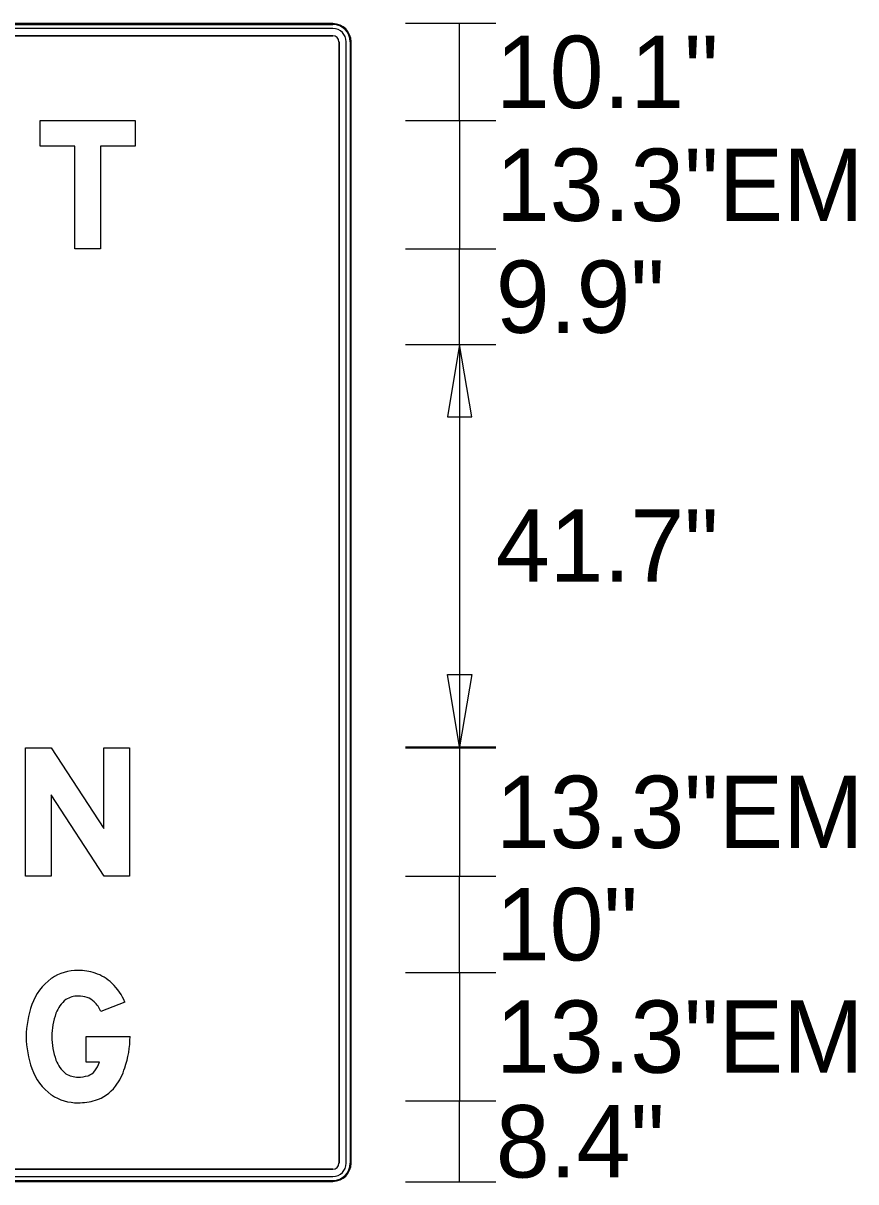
# Model space of a CAD drawing. Extents: x 1806251 to 1809821, y 414895 to 422886.
# Drawn here: x 1809677.976 to 1809678.839, y 415051.78 to 415052.981 of the extents above; entities that cross this region are included whole.
import ezdxf

# ---------------------------------------------------------------- set-up
doc = ezdxf.new("R2010")
doc.units = 0
for name, color, linetype in [('GSBWFILL', 7, 'Continuous'), ('GSCOLORFILL', 7, 'Continuous'), ('GSDIMS', 7, 'Continuous'), ('GSOUTLINE', 7, 'Continuous')]:
    doc.layers.add(name, color=color, linetype=linetype)

msp = doc.modelspace()

# ---------------------------------------------------------------- linework, layer by layer
at = {"layer": 'GSBWFILL'}
for p, q in [((1809678.2972, 415052.9805), (1809676.8938, 415052.9805)), ((1809678.2972, 415052.9755), (1809676.8938, 415052.9755)), ((1809676.8938, 415052.968), (1809678.2972, 415052.968)), ((1809678.3035, 415052.9617), (1809678.3035, 415051.7993)), ((1809678.311, 415051.7993), (1809678.311, 415052.9617)), ((1809678.316, 415051.7993), (1809678.316, 415052.9617)), ((1809678.2972, 415051.793), (1809676.8938, 415051.793)), ((1809676.8938, 415051.7855), (1809678.2972, 415051.7855)), ((1809676.8938, 415051.7805), (1809678.2972, 415051.7805))]:
    msp.add_line(p, q, dxfattribs=at)
for points in [[(1809678.0563, 415052.747), (1809678.0297, 415052.747), (1809678.0297, 415052.8534), (1809677.9938, 415052.8534), (1809677.9938, 415052.88), (1809678.0922, 415052.88), (1809678.0922, 415052.8534), (1809678.0563, 415052.8534)], [(1809677.9786, 415052.23), (1809678.0052, 415052.23), (1809678.0598, 415052.1462), (1809678.0598, 415052.23), (1809678.0864, 415052.23), (1809678.0864, 415052.097), (1809678.0601, 415052.097), (1809678.0052, 415052.1812), (1809678.0052, 415052.097), (1809677.9786, 415052.097)]]:
    msp.add_lwpolyline(points, close=True, dxfattribs=at)
for points in [[(1809678.0817, 415051.9662), (1809678.0568, 415051.9567)], [(1809678.0553, 415051.9039), (1809678.0415, 415051.9039), (1809678.0415, 415051.9305), (1809678.087, 415051.9305)]]:
    msp.add_lwpolyline(points, dxfattribs=at)
for centre, radius, start, end in [((1809678.2972, 415052.9617), 0.0188, 0, 90), ((1809678.2972, 415052.9617), 0.0138, 0, 90), ((1809678.2972, 415052.9617), 0.00625, 0, 90), ((1809678.2972, 415051.7993), 0.0138, 270, 0), ((1809678.2972, 415051.7993), 0.00625, 270, 0), ((1809678.2972, 415051.7993), 0.0188, 270, 0)]:
    msp.add_arc(centre, radius, start, end, dxfattribs=at)
for centre, major_axis, start_param, end_param in [((1809678.0331, 415051.9482), (0, 0.0509), 6.282946, 6.85835), ((1809678.0331, 415051.9419), (0, 0.0572), 5.968128, 6.283185), ((1809678.0368, 415051.9533), (0, 0.0452), 5.51497, 5.968128), ((1809678.0397, 415051.9442), (0, 0.0579), 0.634329, 1.227998), ((1809678.0269, 415051.943), (0, 0.0595), 5.112302, 5.51497), ((1809678.0397, 415051.9442), (0, 0.0313), 0.660238, 1.227998), ((1809678.0331, 415051.9481), (0, 0.0244), 6.282815, 6.826868), ((1809678.0331, 415051.9419), (0, 0.0306), 5.968128, 6.283185), ((1809678.0368, 415051.9533), (0, 0.0186), 5.51497, 5.968128), ((1809678.0844, 415051.9289), (0, 0.1051), 1.233536, 1.555728), ((1809678.0269, 415051.943), (0, 0.0329), 5.141395, 5.51497), ((1809678.0784, 415051.9305), (0, 0.0724), 1.228714, 1.570494), ((1809678.0844, 415051.9321), (0, 0.1051), 1.585865, 1.908057), ((1809678.0784, 415051.9305), (0, 0.0724), 1.571362, 1.913142), ((1809677.9897, 415051.9305), (0, 0.0973), 4.373891, 4.712389), ((1809678.0397, 415051.9168), (0, 0.0579), 1.913595, 2.507264), ((1809678.0397, 415051.9168), (0, 0.0313), 1.913852, 2.481612), ((1809678.0215, 415051.9166), (0, 0.0362), 4.071542, 4.353904), ((1809678.0215, 415051.9166), (0, 0.0628), 4.071542, 4.414751), ((1809678.0331, 415051.9128), (0, 0.0243), 2.597779, 3.141832), ((1809678.0331, 415051.924), (0, 0.0355), 3.141503, 3.435382), ((1809678.0394, 415051.9032), (0, 0.0138), 3.435472, 4.071542), ((1809678.0394, 415051.9032), (0, 0.0404), 3.435472, 4.071542), ((1809678.0331, 415051.9128), (0, 0.0509), 2.566428, 3.141832), ((1809678.0331, 415051.924), (0, 0.0621), 3.141593, 3.435472)]:
    msp.add_ellipse(centre, major_axis=major_axis, ratio=0.999994, start_param=start_param, end_param=end_param, dxfattribs=at)
at = {"layer": 'GSCOLORFILL'}
for p, q in [((1809678.2972, 415052.9805), (1809676.8938, 415052.9805)), ((1809678.2972, 415052.9805), (1809676.8938, 415052.9805)), ((1809676.8938, 415052.9797), (1809678.2972, 415052.9797)), ((1809678.2972, 415052.9755), (1809676.8938, 415052.9755)), ((1809676.8938, 415052.968), (1809678.2972, 415052.968)), ((1809678.3035, 415052.9617), (1809678.3035, 415051.7993)), ((1809678.311, 415051.7993), (1809678.311, 415052.9617)), ((1809678.3152, 415052.9617), (1809678.3152, 415051.7993)), ((1809678.316, 415051.7993), (1809678.316, 415052.9617)), ((1809678.316, 415051.7993), (1809678.316, 415052.9617)), ((1809678.2972, 415051.793), (1809676.8938, 415051.793)), ((1809676.8938, 415051.7855), (1809678.2972, 415051.7855)), ((1809678.2972, 415051.7812), (1809676.8938, 415051.7812)), ((1809676.8938, 415051.7805), (1809678.2972, 415051.7805)), ((1809676.8938, 415051.7805), (1809678.2972, 415051.7805))]:
    msp.add_line(p, q, dxfattribs=at)
for points in [[(1809678.0563, 415052.747), (1809678.0297, 415052.747), (1809678.0297, 415052.8534), (1809677.9938, 415052.8534), (1809677.9938, 415052.88), (1809678.0922, 415052.88), (1809678.0922, 415052.8534), (1809678.0563, 415052.8534)], [(1809677.9786, 415052.23), (1809678.0052, 415052.23), (1809678.0598, 415052.1462), (1809678.0598, 415052.23), (1809678.0864, 415052.23), (1809678.0864, 415052.097), (1809678.0601, 415052.097), (1809678.0052, 415052.1812), (1809678.0052, 415052.097), (1809677.9786, 415052.097)]]:
    msp.add_lwpolyline(points, close=True, dxfattribs=at)
for points in [[(1809678.0817, 415051.9662), (1809678.0568, 415051.9567)], [(1809678.0553, 415051.9039), (1809678.0415, 415051.9039), (1809678.0415, 415051.9305), (1809678.087, 415051.9305)]]:
    msp.add_lwpolyline(points, dxfattribs=at)
for centre, radius, start, end in [((1809678.2972, 415052.9617), 0.0188, 0, 90), ((1809678.2972, 415052.9617), 0.0188, 0, 90), ((1809678.2972, 415052.9617), 0.018, 0, 90), ((1809678.2972, 415052.9617), 0.0138, 0, 90), ((1809678.2972, 415052.9617), 0.00625, 0, 90), ((1809678.2972, 415051.7993), 0.0188, 270, 0), ((1809678.2972, 415051.7993), 0.0138, 270, 0), ((1809678.2972, 415051.7993), 0.00625, 270, 0), ((1809678.2972, 415051.7993), 0.0188, 270, 0), ((1809678.2972, 415051.7993), 0.018, 270, 0)]:
    msp.add_arc(centre, radius, start, end, dxfattribs=at)
for centre, major_axis, start_param, end_param in [((1809678.0331, 415051.9482), (0, 0.0509), 6.282946, 6.85835), ((1809678.0331, 415051.9419), (0, 0.0572), 5.968128, 6.283185), ((1809678.0368, 415051.9533), (0, 0.0452), 5.51497, 5.968128), ((1809678.0397, 415051.9442), (0, 0.0579), 0.634329, 1.227998), ((1809678.0269, 415051.943), (0, 0.0595), 5.112302, 5.51497), ((1809678.0397, 415051.9442), (0, 0.0313), 0.660238, 1.227998), ((1809678.0331, 415051.9481), (0, 0.0244), 6.282815, 6.826868), ((1809678.0331, 415051.9419), (0, 0.0306), 5.968128, 6.283185), ((1809678.0368, 415051.9533), (0, 0.0186), 5.51497, 5.968128), ((1809678.0844, 415051.9289), (0, 0.1051), 1.233536, 1.555728), ((1809678.0269, 415051.943), (0, 0.0329), 5.141395, 5.51497), ((1809678.0784, 415051.9305), (0, 0.0724), 1.228714, 1.570494), ((1809678.0844, 415051.9321), (0, 0.1051), 1.585865, 1.908057), ((1809678.0784, 415051.9305), (0, 0.0724), 1.571362, 1.913142), ((1809677.9897, 415051.9305), (0, 0.0973), 4.373891, 4.712389), ((1809678.0397, 415051.9168), (0, 0.0579), 1.913595, 2.507264), ((1809678.0397, 415051.9168), (0, 0.0313), 1.913852, 2.481612), ((1809678.0215, 415051.9166), (0, 0.0362), 4.071542, 4.353904), ((1809678.0215, 415051.9166), (0, 0.0628), 4.071542, 4.414751), ((1809678.0331, 415051.9128), (0, 0.0243), 2.597779, 3.141832), ((1809678.0331, 415051.924), (0, 0.0355), 3.141503, 3.435382), ((1809678.0394, 415051.9032), (0, 0.0138), 3.435472, 4.071542), ((1809678.0394, 415051.9032), (0, 0.0404), 3.435472, 4.071542), ((1809678.0331, 415051.9128), (0, 0.0509), 2.566428, 3.141832), ((1809678.0331, 415051.924), (0, 0.0621), 3.141593, 3.435472)]:
    msp.add_ellipse(centre, major_axis=major_axis, ratio=0.999994, start_param=start_param, end_param=end_param, dxfattribs=at)
at = {"layer": 'GSDIMS'}
for p, q in [((1809678.3723, 415052.981), (1809678.466, 415052.981)), ((1809678.4285, 415052.88), (1809678.4285, 415052.981)), ((1809678.3723, 415052.88), (1809678.466, 415052.88)), ((1809678.3723, 415052.88), (1809678.466, 415052.88)), ((1809678.4285, 415052.88), (1809678.4285, 415052.747)), ((1809678.3723, 415052.747), (1809678.466, 415052.747)), ((1809678.3723, 415052.747), (1809678.466, 415052.747)), ((1809678.4285, 415052.648), (1809678.4285, 415052.747)), ((1809678.3723, 415052.648), (1809678.466, 415052.648)), ((1809678.3723, 415052.648), (1809678.466, 415052.648)), ((1809678.4285, 415052.648), (1809678.4285, 415052.231)), ((1809678.3723, 415052.231), (1809678.466, 415052.231)), ((1809678.3723, 415052.23), (1809678.466, 415052.23)), ((1809678.4285, 415052.23), (1809678.4285, 415052.097)), ((1809678.3723, 415052.097), (1809678.466, 415052.097)), ((1809678.3723, 415052.097), (1809678.466, 415052.097)), ((1809678.4285, 415051.997), (1809678.4285, 415052.097)), ((1809678.3723, 415051.997), (1809678.466, 415051.997)), ((1809678.3723, 415051.997), (1809678.466, 415051.997)), ((1809678.4285, 415051.997), (1809678.4285, 415051.864)), ((1809678.3723, 415051.864), (1809678.466, 415051.864)), ((1809678.3723, 415051.864), (1809678.466, 415051.864)), ((1809678.4285, 415051.78), (1809678.4285, 415051.864)), ((1809678.3723, 415051.78), (1809678.466, 415051.78))]:
    msp.add_line(p, q, dxfattribs=at)
for points in [[(1809678.4285, 415052.648), (1809678.416, 415052.573), (1809678.441, 415052.573)], [(1809678.4285, 415052.231), (1809678.416, 415052.306), (1809678.441, 415052.306)]]:
    msp.add_lwpolyline(points, close=True, dxfattribs=at)
at = {"layer": 'GSOUTLINE'}
for p, q in [((1809678.2972, 415052.9805), (1809676.8938, 415052.9805)), ((1809678.2972, 415052.9755), (1809676.8938, 415052.9755)), ((1809678.2972, 415052.968), (1809676.8938, 415052.968)), ((1809678.3035, 415051.7993), (1809678.3035, 415052.9617)), ((1809678.311, 415051.7993), (1809678.311, 415052.9617)), ((1809678.316, 415051.7993), (1809678.316, 415052.9617)), ((1809676.8938, 415051.793), (1809678.2972, 415051.793)), ((1809676.8938, 415051.7855), (1809678.2972, 415051.7855)), ((1809676.8938, 415051.7805), (1809678.2972, 415051.7805))]:
    msp.add_line(p, q, dxfattribs=at)
for points in [[(1809678.0563, 415052.747), (1809678.0297, 415052.747), (1809678.0297, 415052.8534), (1809677.9938, 415052.8534), (1809677.9938, 415052.88), (1809678.0922, 415052.88), (1809678.0922, 415052.8534), (1809678.0563, 415052.8534)], [(1809677.9786, 415052.23), (1809678.0052, 415052.23), (1809678.0598, 415052.1462), (1809678.0598, 415052.23), (1809678.0864, 415052.23), (1809678.0864, 415052.097), (1809678.0601, 415052.097), (1809678.0052, 415052.1812), (1809678.0052, 415052.097), (1809677.9786, 415052.097)]]:
    msp.add_lwpolyline(points, close=True, dxfattribs=at)
for points in [[(1809678.0817, 415051.9662), (1809678.0568, 415051.9567)], [(1809678.0553, 415051.9039), (1809678.0415, 415051.9039), (1809678.0415, 415051.9305), (1809678.087, 415051.9305)]]:
    msp.add_lwpolyline(points, dxfattribs=at)
for centre, radius, start, end in [((1809678.2972, 415052.9617), 0.0188, 0, 90), ((1809678.2972, 415052.9617), 0.0138, 0, 90), ((1809678.2972, 415052.9617), 0.00625, 0, 90), ((1809678.2972, 415051.7993), 0.0138, 270, 0), ((1809678.2972, 415051.7993), 0.00625, 270, 0), ((1809678.2972, 415051.7993), 0.0188, 270, 0)]:
    msp.add_arc(centre, radius, start, end, dxfattribs=at)
for centre, major_axis, start_param, end_param in [((1809678.0331, 415051.9482), (0, 0.0509), 6.282946, 6.85835), ((1809678.0331, 415051.9419), (0, 0.0572), 5.968128, 6.283185), ((1809678.0368, 415051.9533), (0, 0.0452), 5.51497, 5.968128), ((1809678.0397, 415051.9442), (0, 0.0579), 0.634329, 1.227998), ((1809678.0269, 415051.943), (0, 0.0595), 5.112302, 5.51497), ((1809678.0397, 415051.9442), (0, 0.0313), 0.660238, 1.227998), ((1809678.0331, 415051.9481), (0, 0.0244), 6.282815, 6.826868), ((1809678.0331, 415051.9419), (0, 0.0306), 5.968128, 6.283185), ((1809678.0368, 415051.9533), (0, 0.0186), 5.51497, 5.968128), ((1809678.0844, 415051.9289), (0, 0.1051), 1.233536, 1.555728), ((1809678.0269, 415051.943), (0, 0.0329), 5.141395, 5.51497), ((1809678.0784, 415051.9305), (0, 0.0724), 1.228714, 1.570494), ((1809678.0844, 415051.9321), (0, 0.1051), 1.585865, 1.908057), ((1809678.0784, 415051.9305), (0, 0.0724), 1.571362, 1.913142), ((1809677.9897, 415051.9305), (0, 0.0973), 4.373891, 4.712389), ((1809678.0397, 415051.9168), (0, 0.0579), 1.913595, 2.507264), ((1809678.0397, 415051.9168), (0, 0.0313), 1.913852, 2.481612), ((1809678.0215, 415051.9166), (0, 0.0362), 4.071542, 4.353904), ((1809678.0215, 415051.9166), (0, 0.0628), 4.071542, 4.414751), ((1809678.0331, 415051.9128), (0, 0.0243), 2.597779, 3.141832), ((1809678.0331, 415051.924), (0, 0.0355), 3.141503, 3.435382), ((1809678.0394, 415051.9032), (0, 0.0138), 3.435472, 4.071542), ((1809678.0394, 415051.9032), (0, 0.0404), 3.435472, 4.071542), ((1809678.0331, 415051.9128), (0, 0.0509), 2.566428, 3.141832), ((1809678.0331, 415051.924), (0, 0.0621), 3.141593, 3.435472)]:
    msp.add_ellipse(centre, major_axis=major_axis, ratio=0.999994, start_param=start_param, end_param=end_param, dxfattribs=at)

# ---------------------------------------------------------------- texts
at = {"layer": 'GSDIMS'}
for s, p in [('10.1"', (1809678.466, 415052.893)), ('13.3"EM', (1809678.466, 415052.776)), ('9.9"', (1809678.466, 415052.66)), ('41.7"', (1809678.466, 415052.402)), ('13.3"EM', (1809678.466, 415052.126)), ('10"', (1809678.466, 415052.0095)), ('13.3"EM', (1809678.466, 415051.893)), ('8.4"', (1809678.466, 415051.7845))]:
    msp.add_text(s, height=0.075, dxfattribs=at).set_placement(p)

doc.saveas('drawing.dxf')
